Omron CX-Programmer project NuevoProyecto (CX-Programmer 9.50)

# PLC NewPLC1: CP1L-E EM

## Program P14_2 (cyclic task 0)
Local symbols
Etapa_0 10.00 BOOL
Etapa_1 10.01 BOOL
Etapa_10 10.10 BOOL
Etapa_11 10.11 BOOL
Etapa_12 10.12 BOOL
Etapa_13 10.13 BOOL
Etapa_14 10.14 BOOL
Etapa_2 10.02 BOOL
Etapa_3 10.03 BOOL
Etapa_4 10.04 BOOL
Etapa_5 10.05 BOOL
Etapa_6 10.06 BOOL
Etapa_7 10.07 BOOL
Etapa_8 10.08 BOOL
Etapa_9 10.09 BOOL
FSd1 15.00 BOOL  ; Flanco Subida d1
FSd2 15.01 BOOL  ; Flanco Subida d2
KD1 100.01 BOOL
KD2 100.03 BOOL
KI1 100.00 BOOL
KI2 100.02 BOOL
a_1 0.01 BOOL
a_2 0.04 BOOL
b_1 0.02 BOOL
b_2 0.05 BOOL
c 0.07 BOOL
d_1 0.03 BOOL
d_2 0.06 BOOL
m 0.00 BOOL

### Section Sección1_Programa_principal
; Etapas 0 ... 14

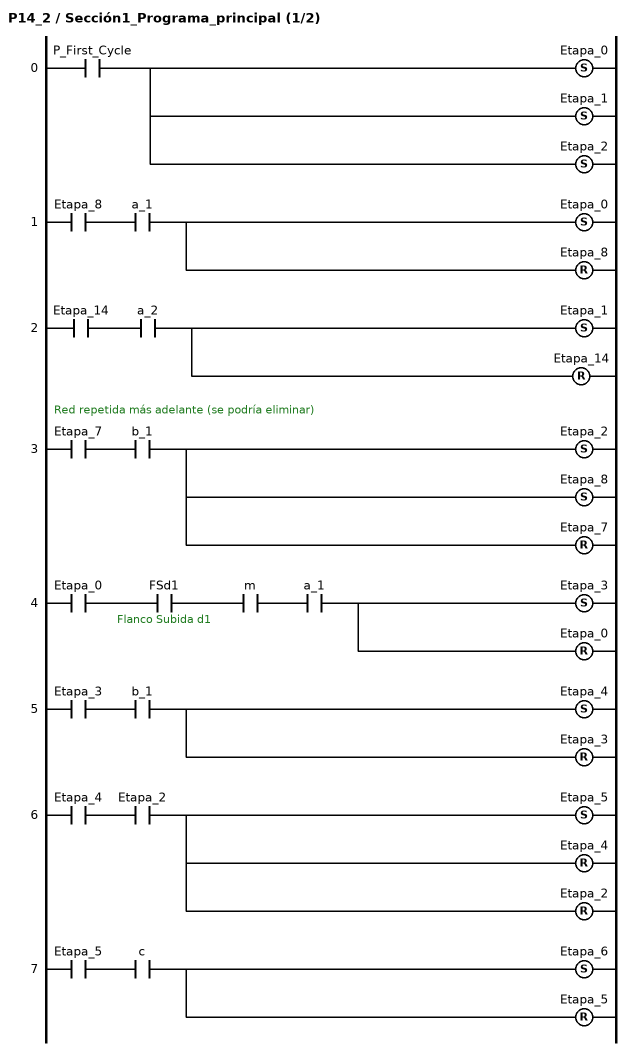
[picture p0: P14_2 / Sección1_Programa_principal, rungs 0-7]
; rung 0
LD P_First_Cycle
SET Etapa_0
SET Etapa_1
SET Etapa_2
; rung 1
LD Etapa_8
AND a_1
SET Etapa_0
RSET Etapa_8
; rung 2
LD Etapa_14
AND a_2
SET Etapa_1
RSET Etapa_14
; rung 3: Red repetida más adelante (se podría eliminar)
LD Etapa_7
AND b_1
SET Etapa_2
SET Etapa_8
RSET Etapa_7
; rung 4
LD Etapa_0
AND FSd1  ; Flanco Subida d1
AND m
AND a_1
SET Etapa_3
RSET Etapa_0
; rung 5
LD Etapa_3
AND b_1
SET Etapa_4
RSET Etapa_3
; rung 6
LD Etapa_4
AND Etapa_2
SET Etapa_5
RSET Etapa_4
RSET Etapa_2
; rung 7
LD Etapa_5
AND c
SET Etapa_6
RSET Etapa_5

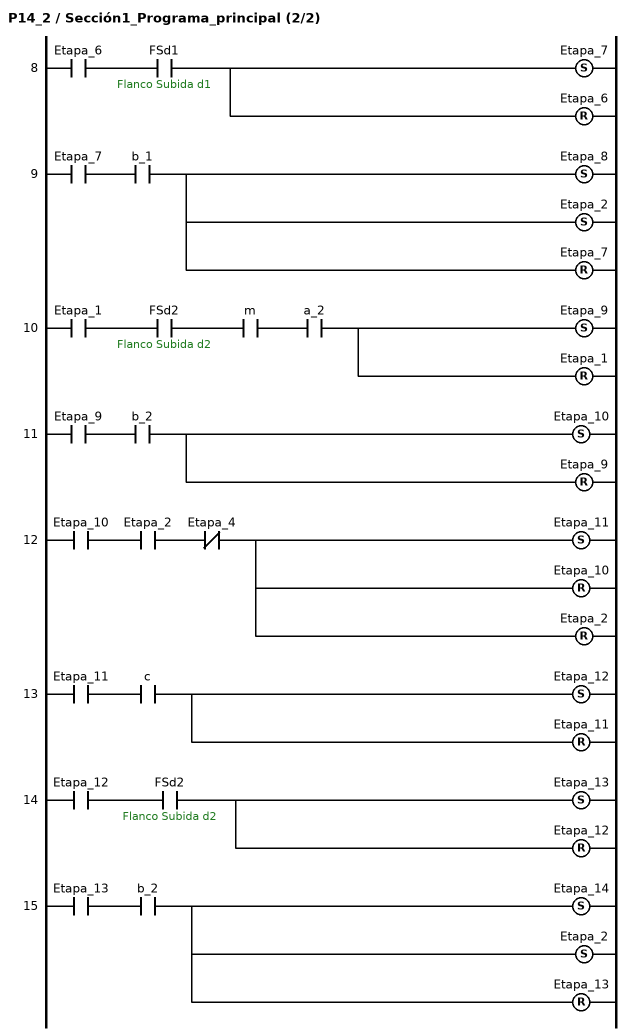
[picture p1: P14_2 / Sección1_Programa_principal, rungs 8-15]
; rung 8
LD Etapa_6
AND FSd1  ; Flanco Subida d1
SET Etapa_7
RSET Etapa_6
; rung 9
LD Etapa_7
AND b_1
SET Etapa_8
SET Etapa_2
RSET Etapa_7
; rung 10
LD Etapa_1
AND FSd2  ; Flanco Subida d2
AND m
AND a_2
SET Etapa_9
RSET Etapa_1
; rung 11
LD Etapa_9
AND b_2
SET Etapa_10
RSET Etapa_9
; rung 12
LD Etapa_10
AND Etapa_2
ANDNOT Etapa_4
SET Etapa_11
RSET Etapa_10
RSET Etapa_2
; rung 13
LD Etapa_11
AND c
SET Etapa_12
RSET Etapa_11
; rung 14
LD Etapa_12
AND FSd2  ; Flanco Subida d2
SET Etapa_13
RSET Etapa_12
; rung 15
LD Etapa_13
AND b_2
SET Etapa_14
SET Etapa_2
RSET Etapa_13

### Section Sección2_Flancos

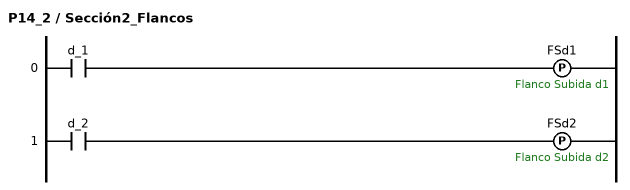
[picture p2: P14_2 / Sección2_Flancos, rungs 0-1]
; rung 0
LD d_1
DIFU(013) FSd1  ; Flanco Subida d1
; rung 1
LD d_2
DIFU(013) FSd2  ; Flanco Subida d2

### Section Sección3_Salidas
; Salidas

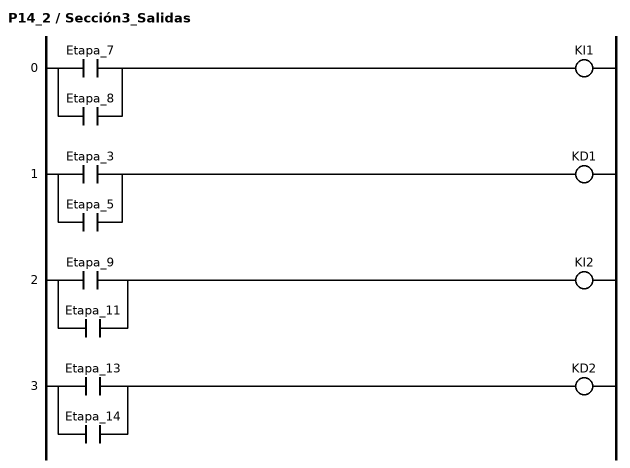
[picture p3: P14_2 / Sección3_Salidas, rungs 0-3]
; rung 0
LD Etapa_7
OR Etapa_8
OUT KI1
; rung 1
LD Etapa_3
OR Etapa_5
OUT KD1
; rung 2
LD Etapa_9
OR Etapa_11
OUT KI2
; rung 3
LD Etapa_13
OR Etapa_14
OUT KD2

### Section Sección4_END
; rung 0
END(001)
